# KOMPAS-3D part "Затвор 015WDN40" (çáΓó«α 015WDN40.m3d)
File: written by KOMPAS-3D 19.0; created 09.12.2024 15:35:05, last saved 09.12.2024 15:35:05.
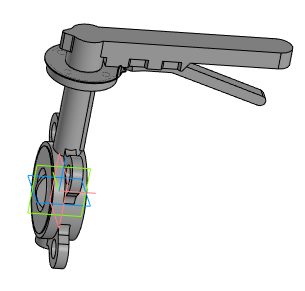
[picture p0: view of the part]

Document properties: Автор: Евгений; Полное имя файла: ..\Затвор 015WDN40.a3d

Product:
- Part/product: Затвор 015WDN40
    Масса: 3.29597

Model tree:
1. Операция без истории:1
